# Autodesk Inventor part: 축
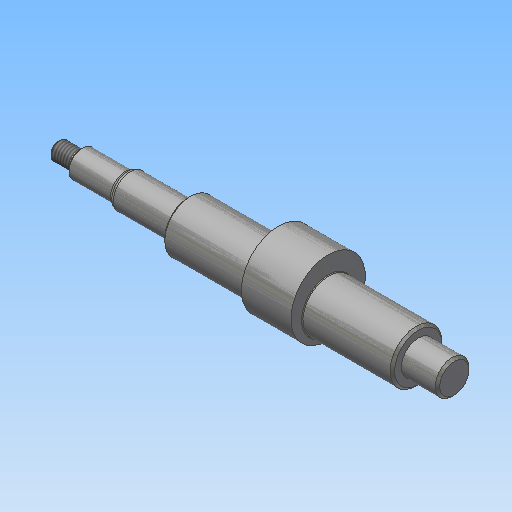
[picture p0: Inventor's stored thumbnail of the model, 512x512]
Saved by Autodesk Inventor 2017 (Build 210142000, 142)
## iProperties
Created: 2015-12
Part Number: 축
Document SubType Name: Modeling
Designer: mdu
Density: 7.86 g/cm^3
Material: 강철, 연강
Appearance: 강철
Author: mdu
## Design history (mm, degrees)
sketch "스케치1"
  geometry: L1 (62, 100.9)-(62, 67.1) reference; L2 (51, 101.2)-(51, 84) reference; L3 (-51, 84)-(-51, 101.2) reference; L4 (-62, 67.1)-(-62, 100.9) reference; L5 (-51.6, 91.5)-(-61.4, 91.5) reference; L6 (51.6, 91.5)-(61.4, 91.5) reference; L7 (67, 84)-(-109, 84); L8 (-77, 64.201)-(-77, 103.799) reference; L9 (67, 84)-(67, 91.5); L10 (67, 91.5)-(51, 91.5); L11 (51, 91.5)-(51, 95.5); L12 (51, 95.5)-(-51, 95.5); L13 (-51, 95.5)-(-51, 91.5); L14 (-51, 91.5)-(-79, 91.5); L15 (-79, 91.5)-(-79, 90); L16 (-79, 90)-(-99, 90); L17 (-99, 90)-(-99, 88); L18 (-99, 88)-(-109, 88); L19 (-109, 88)-(-109, 84); 2 further points
  constraints: 28 end point, 7 parallel, 5 point on line, 4 perpendicular, 2 collinear, 2 horizontal, 1 midpoint, 4 other
  dimensions: "d0" = 5 distance from line of L7.start L1; "d2" = 2 distance between parallel lines of L15 L8; "d3" = 23 diameter of L12 L7; "d4" = 12 diameter of L16 L7; "d7" = 20 distance of L15.end L16.end; "d8" = 10 distance between parallel lines of L17 L19; "d9" = 8 diameter of L18 L7
revolve "회전1" sketch "스케치1" stored, may be unused: angle "d10" = 90 deg
sketch "스케치2"
  geometry: C1 r 11.5 at (84, 0) reference; C2 r 11.5 at (84, 0) reference; C3 r 16.5 at (87, 0); 1 further point
  constraints: 1 centre point, 1 horizontal alignment
  dimensions: "d11" = 33 diameter of C3; "d12" = 3 distance of C3.centre C1.centre
extrude "돌출1" join sketch "스케치2" stored distance "d13" = 22; taper "d14" = 0 deg
chamfer "모따기1" distance "d15" = 1; stored, may be unused: second distance "d16" = 2, angle "d17" = 45 deg
feature "스레드1" dims "d18" = 8, "d19" = 0
node "작업 평면1"
sketch "스케치3"
  geometry: L1 (-5, -2)-(3, -2); L2 (3, 2)-(-5, 2); L3 (-10, -5)-(-10, 5) reference; A1 r 2 centre (3, 0) between (3, -2) and (3, 2); A2 r 2 centre (-5, 0) between (-5, 2) and (-5, -2); 2 further points
  constraints: 4 end point, 4 point on circle, 4 tangent, 2 centre point, 1 horizontal, 1 horizontal alignment, 1 midpoint, 1 parallel
  dimensions: "d20" = 4 distance between parallel lines of L1 L2; "d21" = 12 dimension on A1 A2; "d22" = 3 distance edge to line of A2 L3
extrude "돌출2" cut sketch "스케치3" distance "d23" = 2.5; taper "d24" = 0 deg
fillet "모깎기1" dims "d25" = 0.3
chamfer "모따기2" distance "d27" = 1.65; stored, may be unused: second distance "d28" = 2, angle "d29" = 30 deg
fillet "모깎기3" dims "d30" = 2
node "솔리드1"
node "참조1"
node "참조2"
node "참조3"
node "참조4"
node "참조5"
node "투영된 루프1"
